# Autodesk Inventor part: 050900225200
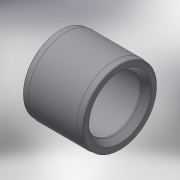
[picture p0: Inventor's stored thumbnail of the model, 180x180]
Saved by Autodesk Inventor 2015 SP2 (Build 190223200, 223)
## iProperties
Created: 2017-11
Part Number: 050900225200
Material: Generic
Description: PLASSON BUSHING-CEMENT PVC 225-200
Document SubType Name: Modeling
Designer: KIM
Density: 1 g/cm^3
Appearance: Default
Author: KIM
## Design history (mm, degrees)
derived "050900.ipt"
feature "Solid1::050900.ipt"
tag "TaggingFeature1"
body "Solid1"
other parameters: "d1" = 225, "d2" = 106, "d3" = 119, "d7" = 11.9, "d11" = 11.9, "d12" = 2.25, "d14" = 2.25, "d15" = 11.9, "d17" = 2.25, "d18" = 2.25, "d19" = 178, "d20" = 2.6, "d21" = 14.1, "D_" = 225, "L_" = 119, "l_" = 106, "z_" = 2
